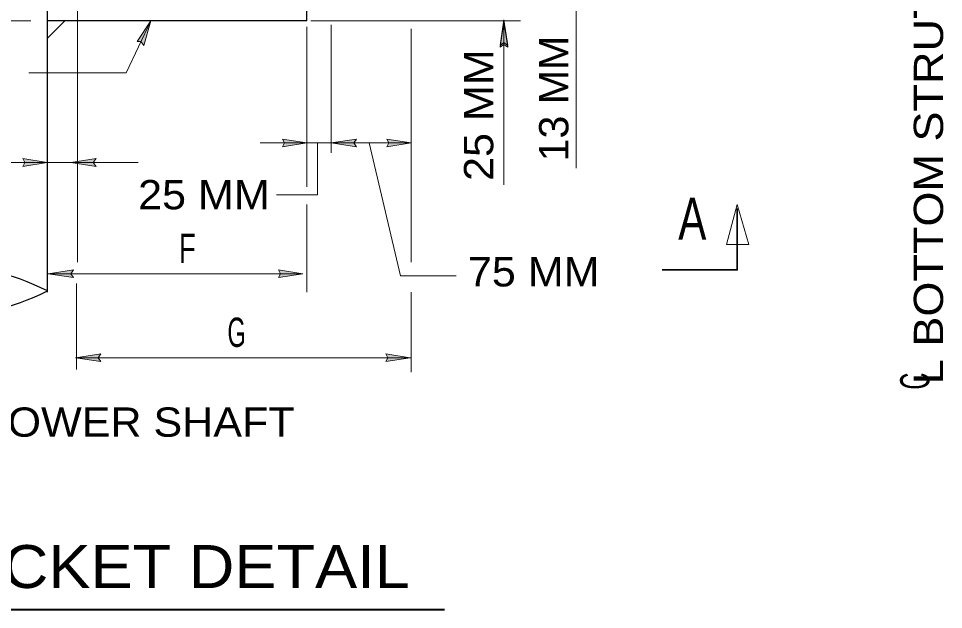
# Model space of a CAD drawing. Extents: x 312601.858 to 312602.699, y 144420.109 to 144420.704.
# Drawn here: x 312602.1684 to 312602.2632, y 144420.3549 to 144420.4155 of the extents above; entities that cross this region are included whole.
import ezdxf
from ezdxf.enums import TextEntityAlignment as Align

# ---------------------------------------------------------------- set-up
doc = ezdxf.new("R2010")
doc.units = 0
doc.header["$LTSCALE"] = 0.0012
for name, color, linetype, lineweight in [('1', 7, 'Continuous', 25), ('2', 7, 'Continuous', 13), ('39', 7, 'Continuous', 13), ('9', 7, 'Continuous', 13)]:
    doc.layers.add(name, color=color, linetype=linetype, lineweight=lineweight)

msp = doc.modelspace()

# ---------------------------------------------------------------- hatches: boundary and pattern name
at = {"layer": '39'}
for points in [[(312602.181, 144420.4131), (312602.1806, 144420.4131), (312602.182, 144420.4152), (312602.1813, 144420.4127)], [(312602.2182, 144420.413), (312602.2186, 144420.4127), (312602.2182, 144420.4153), (312602.2178, 144420.4127)], [(312602.2182, 144420.4128), (312602.2186, 144420.4125), (312602.2182, 144420.4151), (312602.2178, 144420.4125)], [(312602.1957, 144420.4027), (312602.1955, 144420.4023), (312602.198, 144420.4027), (312602.1955, 144420.4031)], [(312602.2028, 144420.4027), (312602.2031, 144420.4031), (312602.2005, 144420.4027), (312602.2031, 144420.4023)], [(312602.2064, 144420.4027), (312602.2062, 144420.4023), (312602.2087, 144420.4027), (312602.2062, 144420.4031)], [(312602.2064, 144420.4027), (312602.2062, 144420.4023), (312602.2087, 144420.4027), (312602.2062, 144420.4031)], [(312602.1691, 144420.4007), (312602.1689, 144420.4003), (312602.1714, 144420.4007), (312602.1689, 144420.4011)], [(312602.1691, 144420.4007), (312602.1689, 144420.4003), (312602.1714, 144420.4007), (312602.1689, 144420.4011)], [(312602.1761, 144420.4007), (312602.1764, 144420.4011), (312602.1738, 144420.4007), (312602.1764, 144420.4003)], [(312602.1738, 144420.3893), (312602.1741, 144420.3889), (312602.1715, 144420.3893), (312602.1741, 144420.3897)], [(312602.1738, 144420.3893), (312602.1741, 144420.3889), (312602.1715, 144420.3893), (312602.1741, 144420.3897)], [(312602.1953, 144420.3893), (312602.1951, 144420.3897), (312602.1976, 144420.3893), (312602.1951, 144420.3889)], [(312602.1766, 144420.3807), (312602.1769, 144420.3811), (312602.1743, 144420.3807), (312602.1769, 144420.3803)], [(312602.2063, 144420.3807), (312602.2061, 144420.3803), (312602.2086, 144420.3807), (312602.2061, 144420.3811)]]:
    msp.add_hatch(color=256, dxfattribs=at).paths.add_polyline_path(points)

# ---------------------------------------------------------------- linework, layer by layer
at = {"layer": '1'}
for p, q in [((312602.1714, 144420.4658), (312602.1714, 144420.3874)), ((312602.198, 144420.4152), (312602.198, 144420.4182)), ((312602.198, 144420.4152), (312602.1714, 144420.4152))]:
    msp.add_line(p, q, dxfattribs=at)
at = {"layer": '1', "lineweight": 13}
for p, q in [((312602.2256, 144420.4001), (312602.2256, 144420.4182)), ((312602.1745, 144420.3905), (312602.1745, 144420.4163)), ((312602.1697, 144420.4152), (312602.1384, 144420.4152)), ((312602.2199, 144420.4152), (312602.1984, 144420.4152)), ((312602.2005, 144420.4017), (312602.2005, 144420.4148)), ((312602.2182, 144420.3984), (312602.2182, 144420.4153)), ((312602.198, 144420.3982), (312602.198, 144420.4146)), ((312602.2087, 144420.3905), (312602.2087, 144420.4144)), ((312602.1975, 144420.4027), (312602.1932, 144420.4027)), ((312602.2005, 144420.4027), (312602.1975, 144420.4027)), ((312602.2087, 144420.4027), (312602.2005, 144420.4027)), ((312602.1543, 144420.4007), (312602.1714, 144420.4007)), ((312602.198, 144420.3874), (312602.198, 144420.3964)), ((312602.1976, 144420.3893), (312602.1715, 144420.3893)), ((312602.1744, 144420.3795), (312602.1744, 144420.3883)), ((312602.2087, 144420.3792), (312602.2087, 144420.3874)), ((312602.2087, 144420.3807), (312602.1745, 144420.3807))]:
    msp.add_line(p, q, dxfattribs=at)
for points in [[(312602.182, 144420.4152), (312602.1795, 144420.4099), (312602.1695, 144420.4099)], [(312602.1807, 144420.4007), (312602.1738, 144420.4007), (312602.1714, 144420.4007)]]:
    msp.add_lwpolyline(points, dxfattribs=at)
at = {"layer": '1', "lineweight": 35}
msp.add_lwpolyline([(312602.2421, 144420.396), (312602.2421, 144420.3897), (312602.2344, 144420.3897)], dxfattribs=at)
at = {"layer": '2', "lineweight": 40}
msp.add_line((312602.1221, 144420.3549), (312602.2121, 144420.3549), dxfattribs=at)
at = {"layer": '2'}
for points in [[(312602.1991, 144420.4027), (312602.1991, 144420.3974), (312602.1949, 144420.3974)], [(312602.2044, 144420.4027), (312602.2076, 144420.3891), (312602.2133, 144420.3891)]]:
    msp.add_lwpolyline(points, dxfattribs=at)
at = {"layer": '2', "lineweight": 25}
for centre, start, end in [((312602.159935, 144420.364641), 63.38393, 116.61607), ((312602.159935, 144420.410439), 243.38393, 296.61607)]:
    msp.add_arc(centre, 0.025613, start, end, dxfattribs=at)
at = {"layer": '39'}
for points in [[(312602.181, 144420.4131), (312602.1806, 144420.4131), (312602.182, 144420.4152), (312602.1813, 144420.4127)], [(312602.2182, 144420.413), (312602.2186, 144420.4127), (312602.2182, 144420.4153), (312602.2178, 144420.4127)], [(312602.2182, 144420.4128), (312602.2186, 144420.4125), (312602.2182, 144420.4151), (312602.2178, 144420.4125)], [(312602.1957, 144420.4027), (312602.1955, 144420.4023), (312602.198, 144420.4027), (312602.1955, 144420.4031)], [(312602.2028, 144420.4027), (312602.2031, 144420.4031), (312602.2005, 144420.4027), (312602.2031, 144420.4023)], [(312602.2064, 144420.4027), (312602.2062, 144420.4023), (312602.2087, 144420.4027), (312602.2062, 144420.4031)], [(312602.2064, 144420.4027), (312602.2062, 144420.4023), (312602.2087, 144420.4027), (312602.2062, 144420.4031)], [(312602.1691, 144420.4007), (312602.1689, 144420.4003), (312602.1714, 144420.4007), (312602.1689, 144420.4011)], [(312602.1691, 144420.4007), (312602.1689, 144420.4003), (312602.1714, 144420.4007), (312602.1689, 144420.4011)], [(312602.1761, 144420.4007), (312602.1764, 144420.4011), (312602.1738, 144420.4007), (312602.1764, 144420.4003)], [(312602.1738, 144420.3893), (312602.1741, 144420.3889), (312602.1715, 144420.3893), (312602.1741, 144420.3897)], [(312602.1738, 144420.3893), (312602.1741, 144420.3889), (312602.1715, 144420.3893), (312602.1741, 144420.3897)], [(312602.1953, 144420.3893), (312602.1951, 144420.3897), (312602.1976, 144420.3893), (312602.1951, 144420.3889)], [(312602.1766, 144420.3807), (312602.1769, 144420.3811), (312602.1743, 144420.3807), (312602.1769, 144420.3803)], [(312602.2063, 144420.3807), (312602.2061, 144420.3803), (312602.2086, 144420.3807), (312602.2061, 144420.3811)]]:
    msp.add_lwpolyline(points, close=True, dxfattribs=at)
at = {"layer": '9'}
for points in [[(312602.1714, 144420.4134), (312602.1732, 144420.4152), (312602.1714, 144420.4152)], [(312602.241, 144420.3923), (312602.2433, 144420.3923), (312602.2421, 144420.3964)]]:
    msp.add_lwpolyline(points, close=True, dxfattribs=at)

# ---------------------------------------------------------------- texts
at = {"layer": '2'}
for s, width, p in [('L BOTTOM STRUT', 1.15, (312602.2632, 144420.3981)), ('13 MM', 1.05, (312602.2248, 144420.40725)), ('25 MM', 1.1, (312602.2171, 144420.40555)), ('C', 0.6, (312602.2618, 144420.3783))]:
    msp.add_text(s, height=0.003, rotation=90, dxfattribs=dict(at, width=width)).set_placement(p, align=Align.CENTER)
for s, height, width, p in [('25 MM', 0.003, 1.1, (312602.18745, 144420.3959)), ('A', 0.0043, 0.75, (312602.2375, 144420.3928)), ('F', 0.003, 0.7, (312602.18575, 144420.3904)), ('75 MM', 0.003, 1.1, (312602.22125, 144420.388)), ('G', 0.003, 0.6, (312602.1908, 144420.3818)), ('L TOWER SHAFT', 0.003, 1.1, (312602.17885, 144420.3726)), ('BOTTOM BRACKET DETAIL', 0.0044, 1.1, (312602.1663, 144420.3571))]:
    msp.add_text(s, height=height, dxfattribs=dict(at, width=width)).set_placement(p, align=Align.CENTER)

doc.saveas('drawing.dxf')
